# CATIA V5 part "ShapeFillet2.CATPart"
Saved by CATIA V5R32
Part number: Part1
Bounding box of the stored display mesh (mm): x 2636.929 to 2658.584, y 475.412 to 576.341, z 2218.145 to 2468.369
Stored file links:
  D:\PROJECTS\Project 2022\CATIA V5 6R 2022\Resources\Part Files\c17_catia_v6_6r2022_prt\ShapeFillet2.CATPart
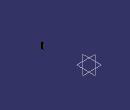
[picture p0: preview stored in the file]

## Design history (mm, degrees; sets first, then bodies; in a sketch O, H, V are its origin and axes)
Set1
  DatumSurface1 to DatumSurface4
  Fillet1: type BiTangent, Element1 DatumSurface2, Element2 DatumSurface1, Radius 3
  Trim1: Element1 DatumSurface3, Element2 Fillet1
  Fillet2: type BiTangent, Element1 DatumSurface4, Element2 Trim1, Radius 4, FacesToKeep face of Fillet1
Body1 (main body)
